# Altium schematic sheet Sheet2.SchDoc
size A4
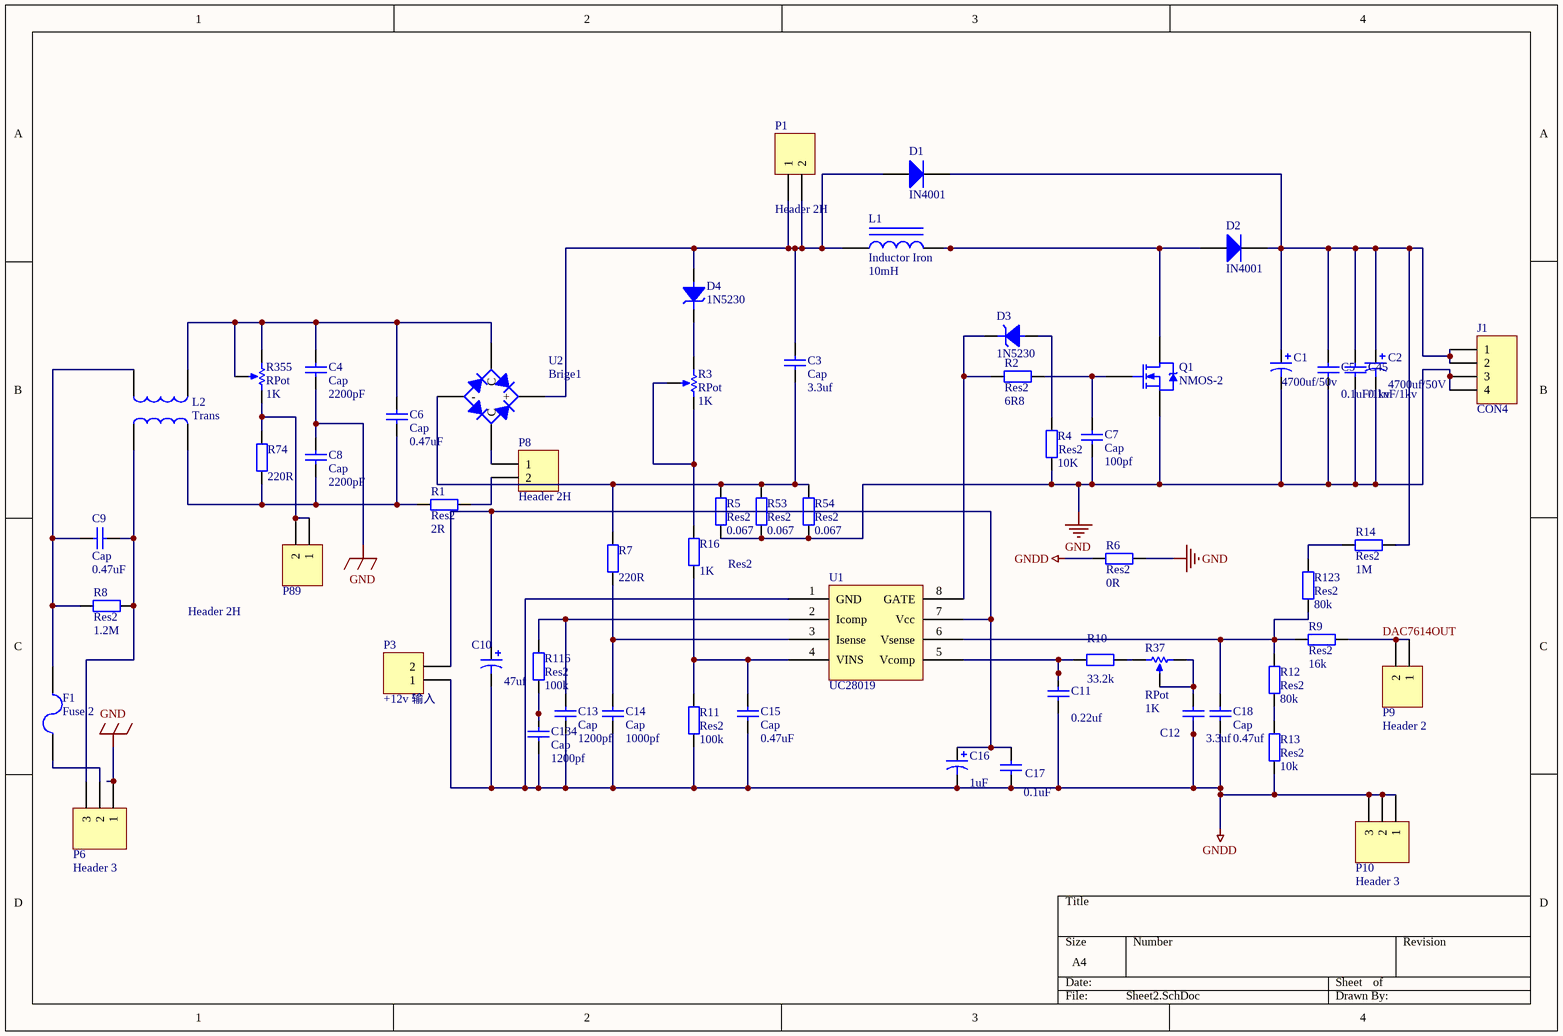
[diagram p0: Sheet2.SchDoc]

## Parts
C1  value 4700uf/50v  [RB7.6-15]  (hidden comment: Cap Pol1)
C2  value 4700uf/50V  [RB7.6-15]  (hidden comment: Cap Pol1)
C3  Cap  value 3.3uf  [RAD-0.3]
C4  Cap  value 2200pF  [RAD-0.3]
C5  value 0.1uF/1kv  [RAD-0.3]  (hidden comment: Cap)
C6  Cap  value 0.47uF  [RAD-0.3]
C7  Cap  value 100pf  [RAD-0.3]
C8  Cap  value 2200pF  [RAD-0.3]
C9  Cap  value 0.47uF  [RAD-0.3]
C10  value 47uf  [CAPPR5-5x5]  (hidden comment: Cap Pol1)
C11  value 0.22uf  [RAD-0.3]  (hidden comment: Cap)
C12  value 3.3uf  [RAD-0.3]  (hidden comment: Cap)
C13  Cap  value 1200pf  [RAD-0.3]
C14  Cap  value 1000pf  [RAD-0.3]
C15  Cap  value 0.47uF  [RAD-0.3]
C16  value 1uF  [CAPPR5-5x5]
C17  value 0.1uF  [RAD-0.3]  (hidden comment: Cap)
C18  Cap  value 0.47uf  [RAD-0.3]
C45  value 0.1uF/1kv  [RAD-0.3]  (hidden comment: Cap)
C134  Cap  value 1200pf  [RAD-0.3]
D1  IN4001  [DIODE0.4]
D2  IN4001  [DO-204AL]
D3  1N5230  [SOD27]
D4  1N5230  [SOD27]
F1  Fuse 2  [PIN-W2/E2.8]
J1  CON4  [COM4-3.5]
L1  Inductor Iron  value 10mH  [AXIAL-0.9]
L2  Trans  [TRANS]
P1  Header 2H  [HDR1X2H]
P3  +12v 输入  [HDR1X2H]
P6  Header 3  [HDR1X3]
P8  Header 2H  [HDR1X2H]
P9  Header 2  [HDR1X2]
P10  Header 3  [HDR1X3]
P89  Header 2H  [HDR1X2H]
Q1  NMOS-2  [TO-220AB]
R1  Res2  value 2R  [AXIAL-0.4]
R2  Res2  value 6R8  [AXIAL-0.4]
R3  RPot  value 1K  [VR5]
R4  Res2  value 10K  [AXIAL-0.4]
R5  Res2  value 0.067  [AXIAL-0.4]
R6  Res2  value 0R  [AXIAL-0.4]
R7  value 220R  [AXIAL-0.4]  (hidden comment: Res2)
R8  Res2  value 1.2M  [AXIAL-0.4]
R9  Res2  value 16k  [AXIAL-0.4]
R10  value 33.2k  [AXIAL-0.4]  (hidden comment: Res2)
R11  Res2  value 100k  [AXIAL-0.4]
R12  Res2  value 80k  [AXIAL-0.4]
R13  Res2  value 10k  [AXIAL-0.4]
R14  Res2  value 1M  [AXIAL-0.4]
R16  Res2  value 1K  [AXIAL-0.4]
R37  RPot  value 1K  [VR5]
R53  Res2  value 0.067  [AXIAL-0.4]
R54  Res2  value 0.067  [AXIAL-0.4]
R74  value 220R  [AXIAL-0.4]  (hidden comment: Res2)
R116  Res2  value 100k  [AXIAL-0.4]
R123  Res2  value 80k  [AXIAL-0.4]
R355  RPot  value 1K  [VR5]
U1  UC28019  [DIP8]
U2  Brige1  [Brige-3A]

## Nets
GND: C1.2 C2.2 C4.2 C5.2 C7.1 C8.1 C45.2 J1.3 J1.4 P6.1 Q1.3(S) R4.1 R5.1 R6.2 R53.1 R54.1
GNDD: C10.2 C11.1 C12.1 C13.1 C14.1 C15.1 C16.2 C17.1 C18.1 C134.1 P3.1 P10.1 P10.2 P10.3 R6.1 R11.1 R13.1 U1.1(GND)
DAC7614OUT: P9.1 P9.2 R9.2
NetC1_1: C1.1 C2.1 C5.1 C45.1 D1.2(K) D2.2(K) J1.1 J1.2 R14.1
NetC3_1: C3.1 R5.2 R7.1 R53.2 R54.2 U2.4(-)
NetC3_2: C3.2 D1.1(A) D4.1(P) L1.1 P1.1 P1.2 U2.1(+)
NetC4_1: C4.1 C6.1 L2.1 R355.1(TOP) R355.3(TAP) U2.2(C)
NetC6_2: C6.2 C8.2 L2.3 R1.1 R74.2
NetC7_2: C7.2 Q1.1(G) R2.1
NetC9_1: C9.1 L2.4 P6.3 R8.2
NetC9_2: C9.2 F1.2 L2.2 R8.1
NetC10_1: C10.1 C16.1 C17.2 P3.2 U1.7(Vcc)
NetC11_2: C11.2 R10.2 U1.5(Vcomp)
NetC12_2: C12.2 R37.2(BOT) R37.3(TAP)
NetC13_2: C13.2 R116.2 U1.2(Icomp)
NetC14_2: C14.2 R7.2 U1.3(Isense)
NetC15_2: C15.2 R11.2 R16.1 U1.4(VINS)
NetC18_2: C18.2 R9.1 R12.2 R123.1 U1.6(Vsense)
NetC134_2: C134.2 R116.1
NetD2_1: D2.1(A) L1.2 Q1.2(D)
NetD3_1: D3.1(P) R4.2
NetD3_2: D3.2(N) R2.2 U1.8(GATE)
NetD4_2: D4.2(N) R3.1(TOP)
NetF1_1: F1.1 P6.2
NetP8_1: P8.1 U2.3(C)
NetP8_2: P8.2 R1.2
NetP89_1: P89.1 P89.2 R74.1 R355.2(BOT)
NetR3_2: R3.2(BOT) R3.3(TAP) R16.2
NetR10_1: R10.1 R37.1(TOP)
NetR12_1: R12.1 R13.2
NetR14_2: R14.2 R123.2

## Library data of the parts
C1 C2 C10 C16 = Cap Pol1: Polarized Capacitor (Radial)
C3-C9 C11-C15 C17 C18 C45 C134 = Cap: Capacitor
D1 D2 = Diode: Default Diode
F1 = Fuse 2: Fuse
J1 = CON4: 终端连接器
L1 = Inductor Iron: Magnetic-Core Inductor
L2 = Trans: Transformer
P1 P3 P8 P89 = Header 2H: Header, 2-Pin, Right Angle
P6 P10 = Header 3: Header, 3-Pin
P9 = Header 2: Header, 2-Pin
Q1 = NMOS-2: N-Channel Power MOSFET; Note: Pin 2 is electrically connected to pin 4.
R1 R2 R4-R14 R16 R53 R54 R74 R116 R123 = Res2: Resistor
R3 R37 R355 = RPot: Potentiometer; Sim Note: Enter the Resistance value and the set point into parameter fields.; Set Position: 0.5
U1 = UCC28019
U2 = Brige1: Full Wave Diode Bridge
